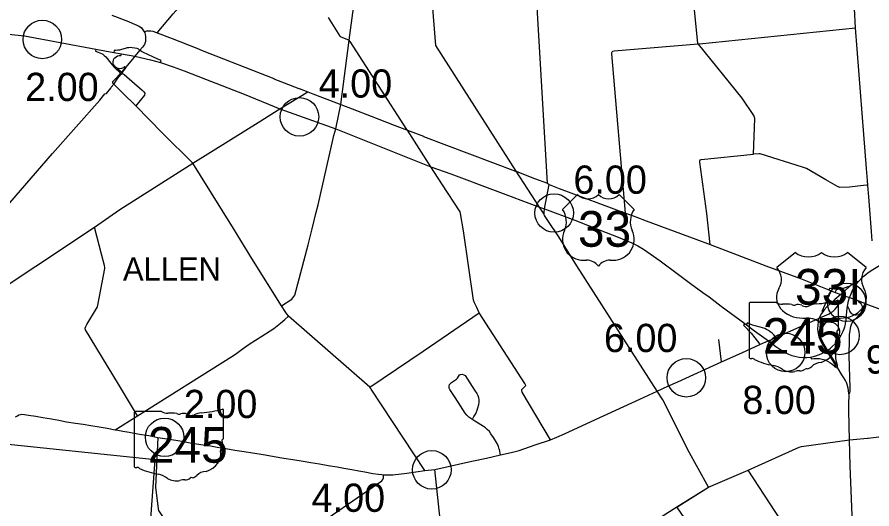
# Model space of a CAD drawing. Extents: x 1659811 to 1934326, y 644115 to 934867.
# Drawn here: x 1685346 to 1718647, y 810108 to 829276 of the extents above; entities that cross this region are included whole.
import ezdxf

# ---------------------------------------------------------------- set-up
doc = ezdxf.new("R2010")
doc.units = 0
for name, color, linetype in [('Default', 7, 'Continuous'), ('GM_X_City_Street', 7, 'Continuous'), ('GM_X_County', 7, 'Continuous'), ('GM_X_County_Road', 7, 'Continuous'), ('GM_X_Interchange_Ramps', 7, 'Continuous'), ('GM_X_State_Route', 7, 'Continuous'), ('GM_X_State_Shield', 7, 'Continuous'), ('GM_X_Township', 7, 'Continuous'), ('GM_X_Township_Road', 7, 'Continuous'), ('GM_X_Township_Text', 7, 'Continuous'), ('GM_X_US_Route', 7, 'Continuous'), ('GM_X_US_Shield', 7, 'Continuous')]:
    doc.layers.add(name, color=color, linetype=linetype)

msp = doc.modelspace()

# ---------------------------------------------------------------- linework, layer by layer
at = {"layer": 'Default'}
for centre in [(1686331, 828405), (1696346, 825387), (1706268, 821641), (1717664, 818162), (1717404, 816867), (1715286, 816206), (1711419, 815217), (1691093, 812898), (1701503, 811631)]:
    msp.add_circle(centre, 750, dxfattribs=at)
at = {"layer": 'GM_X_City_Street'}
for points in [[(1718412, 818102), (1719214, 817801)], [(1717772, 812794), (1717772, 812794), (1717919, 812815), (1718476, 812864), (1718502, 812867)]]:
    msp.add_lwpolyline(points, dxfattribs=at)
at = {"layer": 'GM_X_County'}
msp.add_lwpolyline([(1688986, 788144), (1689326, 792827), (1689614, 796784), (1690016, 802272), (1690262, 805669), (1690301, 806205), (1690722, 812023), (1682012, 812933), (1681252, 813012), (1680866, 813052), (1674899, 813685), (1674917, 813860), (1675148, 816210), (1675883, 823613), (1676368, 828621), (1676732, 832273), (1676760, 832584), (1676808, 833067), (1677110, 836191), (1677306, 838247), (1677531, 840609), (1677620, 841578), (1678185, 847722), (1678709, 853232)], dxfattribs=at)
at = {"layer": 'GM_X_County_Road'}
for points in [[(1718658, 820561), (1718630, 820924), (1718529, 822266), (1718489, 822718), (1718477, 822901), (1718439, 823377), (1718334, 824702), (1718010, 828857), (1717966, 829605), (1717925, 830719), (1717906, 830881), (1717868, 831024), (1717481, 832074), (1716919, 833606)], [(1706004, 822801), (1705562, 830333), (1705428, 832216), (1705402, 832507), (1705405, 832543)], [(1690797, 828663), (1691427, 829400), (1692007, 830075)], [(1697953, 825871), (1698280, 828372), (1698281, 828377), (1698454, 829635)], [(1689039, 829352), (1689238, 829276)], [(1689238, 829276), (1689586, 829142)], [(1689586, 829142), (1689623, 829128), (1690015, 828964), (1690107, 828920), (1690186, 828852), (1690298, 828707), (1690316, 828658)], [(1690316, 828658), (1690334, 828611), (1690350, 828505), (1690354, 828405), (1690344, 828323), (1690306, 828213), (1690236, 828101), (1690133, 827982), (1689932, 827753), (1689902, 827716)], [(1690298, 828707), (1690398, 828739), (1690468, 828745), (1690550, 828743), (1690628, 828723), (1690797, 828663), (1691382, 828437), (1692343, 828063), (1692562, 827977)], [(1692562, 827977), (1695344, 826877), (1695351, 826874)], [(1689902, 827716), (1689573, 827316), (1689410, 827127), (1689380, 827093), (1689226, 826920), (1689068, 826756), (1689060, 826714), (1689109, 826660)], [(1695652, 818022), (1694494, 819868), (1693776, 821030), (1692495, 823105), (1692187, 823589), (1691011, 824752), (1689966, 825815), (1689447, 826330), (1689109, 826660)], [(1695351, 826874), (1696328, 826498), (1696333, 826496)], [(1696333, 826496), (1696668, 826367), (1696870, 826289), (1696873, 826288)], [(1696873, 826288), (1697510, 826042), (1697511, 826041)], [(1697511, 826041), (1697953, 825871), (1698399, 825699), (1698400, 825698)], [(1697690, 824660), (1697760, 824918), (1697953, 825871)], [(1698400, 825698), (1699142, 825412), (1699144, 825412)], [(1699144, 825412), (1700033, 825069), (1700037, 825067)], [(1700037, 825067), (1700550, 824870), (1701172, 824630), (1701179, 824627)], [(1695652, 818022), (1696050, 818288), (1696172, 818443), (1696679, 820397), (1696840, 821026), (1696930, 821399), (1696985, 821623), (1697071, 821961), (1697659, 824545), (1697690, 824660)], [(1701179, 824627), (1704761, 823275)], [(1704761, 823275), (1704787, 823265), (1705270, 823080), (1705507, 822990)], [(1705507, 822990), (1706004, 822801), (1706071, 822748), (1706467, 822597)], [(1705873, 821641), (1705873, 821663), (1705896, 821800), (1706071, 822748)], [(1706467, 822597), (1706469, 822597), (1709050, 821640)], [(1712283, 810959), (1711478, 812413), (1710572, 814239), (1710502, 814356), (1710283, 814693), (1707152, 819580), (1706447, 820706), (1706022, 821352), (1705897, 821541), (1705873, 821601), (1705873, 821641)], [(1709050, 821640), (1709249, 821564)], [(1709249, 821564), (1709445, 821490), (1709854, 821329), (1711788, 820618)], [(1711788, 820618), (1712341, 820415), (1712783, 820244)], [(1712783, 820244), (1714179, 819705), (1714520, 819579)], [(1714520, 819579), (1715867, 819083)], [(1718070, 818240), (1718385, 818113), (1718412, 818102)], [(1695922, 817625), (1695812, 817767), (1695652, 818022)], [(1689163, 813195), (1690037, 813735), (1693716, 816045), (1693849, 816134), (1694108, 816339), (1694381, 816523), (1694877, 816837), (1695350, 817144), (1695611, 817353), (1695771, 817484), (1695922, 817625)], [(1701228, 811599), (1699142, 814775), (1699128, 814801), (1699088, 814852), (1695922, 817625)], [(1690830, 812897), (1690785, 812059), (1690739, 810959), (1690844, 810108), (1690861, 810052), (1690907, 809963), (1691984, 808356), (1692040, 808256), (1693112, 806915), (1693117, 806909), (1694582, 805824), (1695658, 805219), (1697082, 804413), (1697134, 804364), (1697176, 804296), (1697951, 802902), (1698005, 802814), (1698081, 802747), (1698800, 802164)], [(1718502, 812867), (1719334, 812975), (1719366, 812979), (1719386, 812981)], [(1711088, 810208), (1712283, 810959), (1713826, 811612), (1715808, 812517), (1715907, 812540), (1717772, 812794)], [(1705610, 802589), (1705559, 802684), (1703989, 805593), (1702544, 807891), (1701916, 808910), (1701901, 808964), (1701618, 811646)], [(1701979, 804281), (1703989, 805593), (1706267, 807162), (1707440, 807884), (1711051, 810184), (1711088, 810208)]]:
    msp.add_lwpolyline(points, dxfattribs=at)
at = {"layer": 'GM_X_Interchange_Ramps'}
for points in [[(1688415, 828030), (1688399, 827953), (1688508, 827914), (1688568, 827888), (1688630, 827858), (1688685, 827825), (1688744, 827783), (1688802, 827726), (1688855, 827665), (1688944, 827543), (1689052, 827409), (1689112, 827338), (1689181, 827274), (1689352, 827113), (1689380, 827093)], [(1690133, 827982), (1690107, 828004), (1690086, 828019), (1690058, 828034), (1690019, 828049), (1689935, 828067), (1689835, 828084), (1689772, 828087), (1689705, 828081), (1689635, 828072), (1689552, 828050), (1689417, 828014), (1689336, 827993), (1689269, 827982), (1689195, 827978), (1689128, 827980), (1689109, 827902)], [(1690933, 827500), (1690959, 827581), (1690797, 827650), (1690469, 827804), (1690240, 827915), (1690192, 827940), (1690155, 827962), (1690133, 827982)], [(1689573, 827316), (1689535, 827346), (1689488, 827304), (1689417, 827273), (1689341, 827265), (1689287, 827271), (1689239, 827284), (1689212, 827301), (1689179, 827326), (1689137, 827372), (1689106, 827428), (1689093, 827479), (1689089, 827538), (1689099, 827595), (1689118, 827645), (1689153, 827693), (1689200, 827731), (1689262, 827763), (1689323, 827775), (1689390, 827780), (1689407, 827848)], [(1689410, 827127), (1689378, 827151), (1689235, 827269), (1689239, 827284)], [(1718114, 818955), (1718045, 818987), (1717762, 818758), (1717435, 818462), (1717432, 818459), (1717205, 818264), (1717032, 818112), (1716900, 817994), (1716784, 817867), (1716730, 817793), (1716679, 817723), (1716617, 817612), (1716592, 817543), (1716572, 817488), (1716537, 817288), (1716529, 817105), (1716550, 816948), (1716585, 816815), (1716649, 816663), (1716805, 816384), (1716876, 816267), (1717251, 815653), (1717282, 815602), (1717312, 815614)], [(1717059, 818611), (1717048, 818583), (1716697, 817808), (1716730, 817793)], [(1717762, 818758), (1717727, 818774), (1717642, 818740), (1717565, 818715), (1717476, 818695), (1717403, 818678), (1717325, 818675), (1717239, 818674), (1717172, 818676), (1717102, 818685), (1717035, 818692), (1716996, 818698), (1716975, 818644)], [(1717325, 818675), (1717325, 818663), (1717289, 818654), (1717268, 818641), (1717249, 818622), (1717235, 818596), (1717217, 818548)], [(1717754, 814623), (1717791, 814624), (1717795, 814694), (1717796, 814811), (1717766, 816089), (1717769, 816722), (1717777, 816901), (1717794, 817048), (1717812, 817153), (1717828, 817223), (1717851, 817292), (1717884, 817364), (1717918, 817425), (1717971, 817491), (1718031, 817548), (1718099, 817606), (1718162, 817660), (1718210, 817704), (1718252, 817749), (1718286, 817810), (1718353, 817975), (1718399, 818067), (1718412, 818102)], [(1718385, 818113), (1718371, 818078), (1718284, 817867), (1718267, 817873)], [(1713695, 817334), (1713644, 817267), (1713749, 817161), (1713852, 817054), (1713941, 816955), (1714082, 816781), (1714264, 816542), (1714278, 816509)], [(1714899, 816791), (1714883, 816825), (1714829, 816892), (1714762, 816956), (1714689, 817012), (1714619, 817062), (1714543, 817105), (1714477, 817134), (1714383, 817165), (1714295, 817186), (1714094, 817237), (1713989, 817270), (1713900, 817304), (1713798, 817355), (1713751, 817292)], [(1717295, 815747), (1717264, 815736), (1716922, 816296), (1716792, 816509), (1716719, 816644), (1716669, 816750), (1716638, 816843), (1716618, 816920), (1716606, 817009), (1716618, 817094), (1716639, 817166), (1716685, 817245), (1716741, 817304), (1716806, 817351), (1716882, 817384), (1716966, 817396), (1717058, 817391), (1717140, 817371), (1717219, 817330), (1717274, 817279), (1717320, 817224), (1717348, 817175), (1717367, 817111), (1717379, 817048), (1717381, 816981), (1717368, 816920), (1717356, 816876), (1717438, 816852)], [(1716270, 816027), (1716280, 815959), (1716387, 815966), (1716499, 815971), (1716606, 815966), (1716713, 815946), (1716820, 815912), (1716923, 815868), (1717008, 815819), (1717090, 815759), (1717161, 815696), (1717214, 815638), (1717251, 815653)]]:
    msp.add_lwpolyline(points, dxfattribs=at)
at = {"layer": 'GM_X_State_Route'}
for points in [[(1716716, 817595), (1716988, 817709), (1717036, 817744), (1717123, 817802), (1717213, 817892), (1717284, 817976), (1717348, 818075), (1717424, 818251), (1717495, 818438), (1717523, 818429)], [(1717523, 818429), (1717777, 818344)], [(1717777, 818344), (1717778, 818344), (1717851, 818320), (1718070, 818240), (1718128, 818192), (1718184, 818140), (1718229, 818081), (1718253, 818035), (1718253, 818033)], [(1718253, 818033), (1718263, 818003), (1718268, 817948), (1718267, 817873), (1718247, 817811), (1718219, 817759), (1718185, 817715), (1718148, 817688), (1718120, 817676), (1718036, 817660), (1717991, 817664), (1717915, 817682), (1717868, 817710), (1717814, 817773), (1717790, 817817), (1717771, 817868), (1717749, 817922), (1717696, 818007)], [(1716568, 817532), (1716592, 817543), (1716716, 817595)], [(1714517, 816618), (1714618, 816664), (1714899, 816791), (1715458, 817036), (1716568, 817532)], [(1685285, 813690), (1685360, 813741), (1685407, 813770), (1685473, 813790), (1685535, 813797), (1685628, 813791), (1685788, 813767), (1686078, 813717), (1686351, 813675), (1686683, 813612), (1686968, 813565), (1687268, 813501), (1687621, 813455), (1687915, 813406), (1688214, 813356), (1688537, 813302), (1688853, 813251), (1689163, 813195), (1689201, 813189), (1689466, 813137), (1689718, 813094), (1690111, 813027), (1690483, 812963), (1690830, 812897), (1691279, 812823), (1691680, 812756), (1692092, 812687), (1692509, 812618), (1692876, 812562), (1693134, 812517), (1693477, 812461), (1693834, 812400), (1694195, 812340), (1694511, 812292), (1694774, 812249), (1695008, 812210), (1695357, 812150), (1695737, 812079), (1696090, 812027), (1696493, 811962), (1696786, 811917), (1697132, 811862), (1697469, 811804), (1697814, 811750), (1698074, 811697), (1698386, 811647), (1698657, 811596), (1698893, 811553), (1699210, 811493), (1699420, 811461), (1699551, 811445), (1699616, 811442), (1699683, 811438), (1699829, 811432), (1699980, 811437), (1700527, 811506), (1701228, 811599), (1701618, 811646), (1703063, 811966), (1703634, 812091), (1704182, 812217), (1704595, 812305), (1704901, 812379), (1705533, 812611), (1706127, 812806), (1706373, 812906), (1706677, 813035), (1707874, 813586), (1709604, 814388), (1710283, 814693), (1710701, 814889), (1711086, 815066), (1712784, 815834), (1713577, 816197), (1714278, 816509), (1714517, 816618)]]:
    msp.add_lwpolyline(points, dxfattribs=at)
at = {"layer": 'GM_X_State_Shield'}
for p, q in [((1713866, 818118), (1713866, 816005)), ((1714920, 818154), (1713900, 818154)), ((1717347, 817101), (1717347, 818207)), ((1717346, 817101), (1717347, 817101)), ((1690966, 813908), (1689947, 813908)), ((1693393, 812855), (1693393, 813961)), ((1689913, 813872), (1689913, 811759)), ((1693393, 812855), (1693393, 812855))]:
    msp.add_line(p, q, dxfattribs=at)
for centre, major_axis, start_param, end_param in [((1716107, 821035), (3691, 0), 4.814394, 5.042369), ((1717308, 818211), (38.7, 0), 6.141152, 7.989035), ((1713906, 818122), (40.3, 0), 1.712693, 3.28349), ((1715162, 818400), (391, 0), 4.042523, 4.731795), ((1715292, 816968), (1404, 0), 1.404758, 1.657858), ((1715611, 818133), (113, 0), 3.836095, 5.185415), ((1715776, 817889), (235, 0), 0.950623, 2.079405), ((1716079, 818224), (282, 0), 4.081561, 5.145723), ((1716578, 817509), (743, 0), 1.699011, 2.107814), ((1717338, 817020), (60, 0), 1.883978, 3.671073), ((1716956, 816880), (360, 0), 5.934695, 6.695948), ((1717305, 817097), (41.5, 0), 5.05454, 6.418171), ((1716314, 816498), (923, 0), 5.101752, 6.440018), ((1717485, 816638), (262, 0), 2.387724, 3.262537), ((1713906, 816000), (40.7, 0), 3.00124, 4.508301), ((1713913, 816216), (310, 0), 4.665946, 4.897461), ((1713976, 815883), (112, 0), 0.519207, 1.627899), ((1715389, 817781), (2665, 0), 4.195997, 4.488961), ((1714595, 815055), (834, 0), 0.823519, 1.323587), ((1715841, 815714), (282, 0), 4.691044, 5.507374), ((1716096, 815509), (79.4, 0), 1.147584, 2.315152), ((1716062, 815800), (298, 0), 4.937069, 5.64225), ((1716703, 815411), (506, 0), 1.647645, 2.488434), ((1715497, 815872), (529, 0), 4.026481, 4.996735), ((1715802, 815142), (435, 0), 1.495662, 1.94098), ((1689953, 813876), (40.3, 0), 1.712693, 3.28349), ((1691209, 814154), (391, 0), 4.042523, 4.731795), ((1692153, 816789), (3691, 0), 4.814394, 5.042369), ((1693354, 813965), (38.7, 0), 6.141152, 7.989035), ((1691339, 812722), (1404, 0), 1.404758, 1.657858), ((1691657, 813887), (113, 0), 3.836095, 5.185415), ((1691823, 813643), (235, 0), 0.950623, 2.079405), ((1692126, 813978), (282, 0), 4.081561, 5.145723), ((1692624, 813263), (743, 0), 1.699011, 2.107814), ((1693384, 812774), (60, 0), 1.883978, 3.671073), ((1693003, 812634), (360, 0), 5.934695, 6.695948), ((1693352, 812851), (41.5, 0), 5.05454, 6.418171), ((1692360, 812252), (923, 0), 5.101752, 6.440018), ((1693532, 812392), (262, 0), 2.387724, 3.262537), ((1689953, 811754), (40.7, 0), 3.00124, 4.508301), ((1689959, 811970), (310, 0), 4.665946, 4.897461), ((1690023, 811637), (112, 0), 0.519207, 1.627899), ((1691436, 813535), (2665, 0), 4.195997, 4.488961), ((1692749, 811165), (506, 0), 1.647645, 2.488434), ((1690641, 810809), (834, 0), 0.823519, 1.323587), ((1691543, 811626), (529, 0), 4.026481, 4.996735), ((1691849, 810896), (435, 0), 1.495662, 1.94098), ((1691887, 811468), (282, 0), 4.691044, 5.507374), ((1692143, 811263), (79.4, 0), 1.147584, 2.315152), ((1692109, 811554), (298, 0), 4.937069, 5.64225)]:
    msp.add_ellipse(centre, major_axis=major_axis, ratio=0.8, start_param=start_param, end_param=end_param, dxfattribs=at)
at = {"layer": 'GM_X_Township'}
msp.add_lwpolyline([(1718655, 802499), (1718601, 802487), (1718367, 802469), (1718309, 802461), (1716022, 802348), (1715319, 803513), (1712365, 808283), (1711051, 810184), (1712283, 810959), (1711478, 812413), (1710572, 814239), (1710501, 814356), (1710283, 814693), (1707152, 819580), (1706447, 820706), (1706022, 821352), (1705897, 821541), (1705873, 821601), (1705698, 821874), (1704787, 823265), (1701663, 828163), (1701513, 829961)], dxfattribs=at)
at = {"layer": 'GM_X_Township_Road'}
for points in [[(1718489, 822718), (1718424, 822721), (1717777, 822653), (1717401, 822629), (1717306, 822672), (1716858, 822934), (1716097, 823372), (1715939, 823425), (1714298, 823944), (1714256, 823946), (1714032, 823932), (1714080, 825319), (1714076, 825365), (1714045, 825442), (1713596, 826121), (1711892, 828221), (1711882, 828236), (1711871, 828253), (1711607, 830875), (1711599, 830896), (1711581, 830942)], [(1700533, 824896), (1698325, 828327), (1698280, 828372), (1698273, 828379), (1697976, 828492), (1697938, 828537), (1697481, 829256)], [(1711926, 828240), (1718010, 828857)], [(1709050, 821640), (1708517, 827845), (1708516, 827891), (1708526, 827927), (1708552, 827945), (1708610, 827957), (1711882, 828236), (1711926, 828240)], [(1689484, 827167), (1689582, 827285)], [(1689109, 826660), (1689267, 826889), (1689324, 826958), (1689406, 827055), (1689444, 827073), (1689477, 827063), (1689516, 827040), (1690217, 826422), (1690257, 826390)], [(1689444, 827073), (1689477, 827159), (1689484, 827167)], [(1685013, 821982), (1685016, 821987), (1685057, 822036), (1686720, 823963), (1688574, 826041), (1688768, 826282), (1688832, 826302), (1689001, 826502), (1689017, 826545), (1689109, 826660)], [(1690257, 826390), (1690286, 826366), (1690320, 826310), (1690315, 826233), (1689966, 825815)], [(1696315, 826148), (1696668, 826367)], [(1694846, 825237), (1695522, 825656), (1695584, 825695), (1696315, 826148), (1696315, 826148)], [(1683554, 817907), (1686071, 819566), (1688358, 821085), (1689353, 821774), (1692187, 823589), (1694846, 825237), (1694846, 825237)], [(1701896, 822778), (1701466, 823446), (1700550, 824870), (1700533, 824896), (1700533, 824896)], [(1712341, 820415), (1712214, 821616), (1711949, 823618), (1711943, 823668), (1711957, 823718), (1711993, 823724), (1714032, 823932)], [(1706127, 812806), (1705016, 814662), (1705004, 814717), (1705011, 814759), (1705053, 814805), (1705144, 814886), (1705161, 814912), (1705157, 814946), (1705131, 814993), (1703352, 817746), (1703250, 817961), (1703167, 818135), (1703122, 818244), (1702732, 820939), (1702622, 821620), (1702603, 821680), (1701897, 822777), (1701896, 822778)], [(1690037, 813735), (1689292, 814967), (1688005, 817086), (1687999, 817122), (1687998, 817156), (1688021, 817222), (1688062, 817294), (1688438, 817918), (1688461, 817960), (1688488, 818046), (1688560, 818382), (1688767, 819471), (1688762, 819511), (1688751, 819594), (1688630, 820039), (1688358, 821085)], [(1699088, 814852), (1701162, 816255), (1703352, 817746)], [(1712784, 815834), (1712680, 816707)], [(1704134, 812423), (1704131, 812437), (1704098, 812544), (1704042, 812656), (1703901, 812888), (1703803, 813039), (1703748, 813120), (1703662, 813201), (1703590, 813262), (1703511, 813322), (1703311, 813443), (1703181, 813524), (1703065, 813601), (1702949, 813682), (1702868, 813756), (1702800, 813842), (1702615, 814121), (1702408, 814446), (1702255, 814678), (1702199, 814766), (1702180, 814812), (1702176, 814852), (1702178, 814903), (1702197, 814956), (1702224, 814996), (1702271, 815038), (1702350, 815082), (1702429, 815138), (1702464, 815161), (1702498, 815205), (1702536, 815270), (1702582, 815328), (1702626, 815349), (1702691, 815358), (1702754, 815337), (1702798, 815302), (1703162, 814740), (1703255, 814608), (1703292, 814525), (1703320, 814448), (1703334, 814341), (1703332, 814267), (1703320, 814162), (1703276, 814030), (1703251, 813942), (1703216, 813844), (1703144, 813717), (1703086, 813619)], [(1704182, 812217), (1704134, 812423)], [(1717225, 806584), (1717149, 806671), (1717055, 806768), (1716988, 806851), (1714879, 810008), (1713826, 811612)], [(1691137, 805642), (1693112, 806915), (1696503, 809103), (1699554, 811203), (1699597, 811259), (1699607, 811283), (1699624, 811319), (1699626, 811377), (1699616, 811442)]]:
    msp.add_lwpolyline(points, dxfattribs=at)
at = {"layer": 'GM_X_US_Route'}
for points in [[(1679438, 830584), (1679519, 830526), (1680303, 830082), (1680623, 829907), (1680700, 829868), (1680854, 829790), (1681567, 829481), (1682502, 829165), (1682908, 829037), (1683584, 828874), (1684758, 828638), (1685640, 828543), (1688415, 828030), (1689109, 827902), (1689407, 827848), (1689932, 827753)], [(1689932, 827753), (1690543, 827606), (1690933, 827500), (1691424, 827342), (1691852, 827179), (1692681, 826862), (1694193, 826278), (1695584, 825695), (1697760, 824918), (1701466, 823446), (1702247, 823164), (1705698, 821874), (1705896, 821800), (1707070, 821358), (1708057, 820977), (1708768, 820699), (1709301, 820483), (1709533, 820363), (1709743, 820235), (1710393, 819776), (1711056, 819283), (1711581, 818894), (1712060, 818536), (1712301, 818368), (1712775, 818004), (1713695, 817334), (1713751, 817292), (1714076, 817048), (1714618, 816664)], [(1717861, 818553), (1717889, 818617), (1717915, 818665), (1717962, 818743), (1718063, 818890), (1718114, 818955), (1718229, 819079), (1718309, 819162), (1718407, 819248), (1718506, 819316), (1718687, 819438), (1718939, 819588), (1719451, 819862)], [(1715867, 819083), (1716975, 818644), (1717059, 818611), (1717217, 818548), (1717435, 818462), (1717495, 818438)], [(1717722, 818148), (1717741, 818222), (1717778, 818344), (1717808, 818430), (1717861, 818553)], [(1717614, 817306), (1717623, 817346), (1717644, 817473), (1717660, 817632), (1717675, 817817), (1717696, 818007), (1717719, 818136), (1717722, 818148)], [(1717319, 816669), (1717333, 816687), (1717373, 816740), (1717438, 816852), (1717525, 817029), (1717565, 817126), (1717590, 817202), (1717614, 817306)], [(1714618, 816664), (1714909, 816434), (1715063, 816327), (1715200, 816238), (1715399, 816138), (1715530, 816086), (1715697, 816046), (1715811, 816024), (1715958, 816014), (1716117, 816014), (1716270, 816027), (1716464, 816078), (1716670, 816155), (1716876, 816267), (1716876, 816268)], [(1716923, 816296), (1716950, 816312), (1717029, 816373), (1717074, 816411), (1717226, 816554), (1717319, 816669)], [(1717295, 815747), (1717247, 815976), (1717237, 816078), (1717237, 816201), (1717252, 816312), (1717287, 816441), (1717330, 816553), (1717343, 816611), (1717333, 816687)], [(1716876, 816268), (1716922, 816296), (1716923, 816296)], [(1717754, 814623), (1717718, 814815), (1717685, 814950), (1717652, 815032), (1717616, 815111), (1717548, 815220), (1717478, 815327), (1717312, 815614), (1717301, 815711), (1717295, 815747)], [(1717751, 813926), (1717745, 814217), (1717758, 814543), (1717754, 814623)], [(1717849, 806372), (1717850, 806377), (1717907, 806576), (1717932, 806700), (1717939, 806840), (1717947, 807484), (1717934, 807784), (1717899, 809208), (1717801, 811788), (1717772, 812794), (1717751, 813926)]]:
    msp.add_lwpolyline(points, dxfattribs=at)
at = {"layer": 'GM_X_US_Shield'}
for p, q in [((1707177, 822356), (1706597, 821776)), ((1709382, 821776), (1708802, 822356)), ((1715667, 820097), (1714942, 819517)), ((1718422, 819517), (1717697, 820097)), ((1707410, 819803), (1707526, 819803)), ((1708454, 819803), (1708570, 819803)), ((1715957, 817545), (1716102, 817545)), ((1717262, 817545), (1717407, 817545))]:
    msp.add_line(p, q, dxfattribs=at)
for centre, radius, start, end in [((1707584, 822770), 580, 225.573, 314.427), ((1708396, 822770), 580, 225.573, 314.427), ((1705932, 821310), 812, 334.5471, 35.0009), ((1710047, 821310), 812, 144.9991, 205.4529), ((1707400, 820615), 812, 154.8319, 270.6383), ((1708579, 820615), 812, 269.3617, 25.1681), ((1707526, 819223), 580, 36.8699, 90), ((1708454, 819223), 580, 90, 143.1301)]:
    msp.add_arc(centre, radius, start, end, dxfattribs=at)
for centre, major_axis, start_param, end_param in [((1716175, 820512), (-725, 0), 0.795399, 2.346194), ((1717190, 820512), (-725, 0), 0.795399, 2.346194), ((1714110, 819051), (1015, 0), 5.838949, 6.894067), ((1719254, 819051), (-1015, 0), 5.672304, 6.727422), ((1715946, 818357), (1015, 0), 2.702327, 4.723529), ((1717419, 818357), (-1015, 0), 1.559657, 3.580859), ((1716102, 816965), (-725, 0), 3.785094, 4.712389), ((1717262, 816965), (-725, 0), 4.712389, 5.639684)]:
    msp.add_ellipse(centre, major_axis=major_axis, ratio=0.8, start_param=start_param, end_param=end_param, dxfattribs=at)

# ---------------------------------------------------------------- texts
at = {"layer": 'Default'}
for s, p in [('4.00', (1697096, 826137)), ('2.00', (1685660, 826005)), ('6.00', (1707018, 822391)), ('6.00', (1708208, 816221)), ('9.63', (1718408, 815382)), ('8.00', (1713599, 813806)), ('2.00', (1691843, 813648)), ('4.00', (1696819, 809993))]:
    msp.add_text(s, height=1100, dxfattribs=at).set_placement(p)
at = {"layer": 'GM_X_State_Shield'}
for p in [(1714398, 816154), (1690444, 811908)]:
    msp.add_text('245', height=1392.2, dxfattribs=at).set_placement(p)
at = {"layer": 'GM_X_Township_Text'}
msp.add_text('ALLEN', height=900, rotation=0, dxfattribs=at).set_placement((1689472, 819009))
at = {"layer": 'GM_X_US_Shield'}
for s, p in [('33', (1707197, 820325)), ('33I', (1715654, 818067))]:
    msp.add_text(s, height=1392.2, dxfattribs=at).set_placement(p)

doc.saveas('drawing.dxf')
